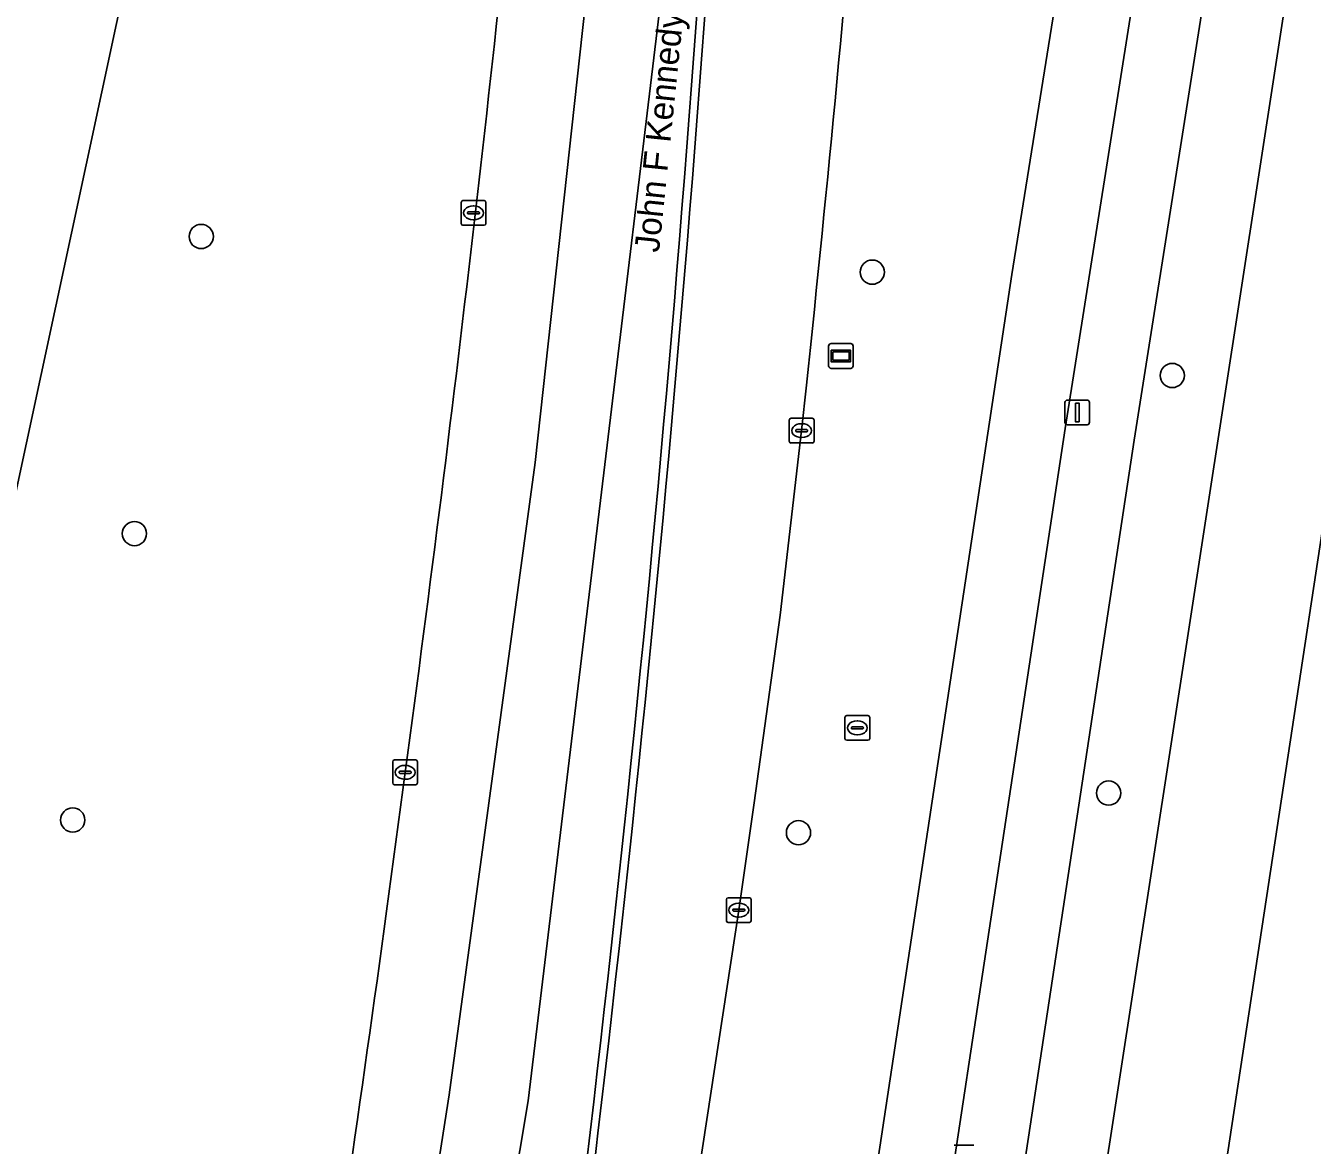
# Model space of a CAD drawing. Extents: x 161758 to 162722, y 384793 to 385405.
# Drawn here: x 161822.4 to 161874.4, y 385053.9 to 385099.1 of the extents above; entities that cross this region are included whole.
import ezdxf

# ---------------------------------------------------------------- set-up
doc = ezdxf.new("R2010")
doc.units = 0
for name, color, linetype in [('IMGEO_Berm_groen', 7, 'Continuous'), ('IMGEO_Boom', 7, 'Continuous'), ('IMGEO_Erf', 7, 'Continuous'), ('IMGEO_Fietspad_open', 7, 'Continuous'), ('IMGEO_Groenvoorziening', 7, 'Continuous'), ('IMGEO_Hek', 7, 'Continuous'), ('IMGEO_Kolk', 7, 'Continuous'), ('IMGEO_Lichtmast', 7, 'Continuous'), ('IMGEO_Openbare_ruimte_label', 7, 'Continuous'), ('IMGEO_Rijbaan_lokaal_open', 7, 'Continuous'), ('IMGEO_Rijbaan_regionaal_gesloten', 7, 'Continuous'), ('IMGEO_Rioolput', 7, 'Continuous'), ('IMGEO_Voetpad_open', 7, 'Continuous'), ('IMGEO_Wegwijzer', 7, 'Continuous')]:
    doc.layers.add(name, color=color, linetype=linetype)

msp = doc.modelspace()

# ---------------------------------------------------------------- linework, layer by layer
at = {"layer": 'IMGEO_Berm_groen'}
for points in [[(161862.222, 385089.066), (161867.535, 385122.216), (161881.319, 385208.219), (161882.409, 385215.357), (161882.64, 385217.117), (161883.068, 385221.062)], [(161842.635, 384958.805), (161843.029, 384961.875), (161848.422, 384997.787), (161862.222, 385089.066)], [(161853.937, 385084.588), (161853.743, 385082.758), (161852.871, 385075.308), (161851.83, 385067.734), (161851.205, 385063.4), (161848.122, 385043.24), (161844.782, 385021.036), (161841.441, 384998.802), (161837.654, 384973.607), (161835.818, 384961.758)]]:
    msp.add_lwpolyline(points, dxfattribs=at)
for points in [[(161832.166, 385127.543), (161825.07, 385129.091), (161797.302, 385000), (161795.542, 384991.822), (161802.405, 384988.861), (161804.796, 385000)], [(161825.07, 385129.091), (161832.166, 385127.543), (161804.796, 385000), (161802.405, 384988.861), (161795.542, 384991.822), (161797.302, 385000)]]:
    msp.add_lwpolyline(points, close=True, dxfattribs=at)
for centre, radius, start, end in [((160707.489, 385222.265), 1140.599, 352.27579, 354.544128), ((160724.749, 385203.725), 1135.456, 353.977202, 355.219785), ((160752.062, 385211.102), 1094.942, 350.170994, 352.54116)]:
    msp.add_arc(centre, radius, start, end, dxfattribs=at)
at = {"layer": 'IMGEO_Boom'}
for centre in [(161829.509, 385090.595), (161856.592, 385089.155), (161868.7, 385084.983), (161826.814, 385078.601), (161866.131, 385068.124), (161824.323, 385067.038), (161853.614, 385066.523)]:
    msp.add_circle(centre, 0.489, dxfattribs=at)
at = {"layer": 'IMGEO_Erf'}
msp.add_lwpolyline([(161880.923, 385119.329), (161863.287, 385003.273), (161862.79, 385000), (161854.635, 384944.828), (161890.389, 384901.27), (161895.384, 384909.442)], dxfattribs=at)
at = {"layer": 'IMGEO_Fietspad_open'}
for points in [[(161873.913, 385143.131), (161885.4, 385214.936), (161882.409, 385215.357), (161881.319, 385208.219), (161867.535, 385122.216), (161862.222, 385089.066), (161848.422, 384997.787), (161843.029, 384961.875), (161842.635, 384958.805)], [(161845.937, 384961.055), (161864.377, 385082.843), (161870.503, 385121.575), (161873.913, 385143.131)]]:
    msp.add_lwpolyline(points, dxfattribs=at)
at = {"layer": 'IMGEO_Groenvoorziening'}
for points in [[(161892.743, 385260.68), (161890.539, 385233.713), (161888.572, 385218.345), (161891.617, 385217.57), (161876.429, 385120.298), (161873.599, 385102.176), (161860.843, 385019.372), (161853.315, 384968.451), (161850.889, 384943.599), (161852.833, 384935.577), (161860.083, 384917.83), (161874.638, 384901.508), (161887.186, 384893.396), (161890.389, 384901.27), (161854.635, 384944.828), (161862.79, 385000), (161863.287, 385003.273), (161880.923, 385119.329), (161887.975, 385165.729), (161892.13, 385191.383), (161913.18, 385282.726), (161913.347, 385283.925), (161913.577, 385286.213)], [(161891.617, 385217.57), (161888.572, 385218.345), (161888.19, 385214.465), (161881.5, 385172.372), (161876.704, 385142.872), (161873.252, 385120.982), (161867.164, 385082.371), (161848.857, 384961.566)], [(161885.599, 384889.495), (161887.186, 384893.396), (161874.638, 384901.508), (161860.083, 384917.83), (161852.833, 384935.577), (161850.889, 384943.599), (161853.315, 384968.451), (161860.843, 385019.372), (161873.599, 385102.176), (161876.429, 385120.298), (161891.617, 385217.57)]]:
    msp.add_lwpolyline(points, dxfattribs=at)
at = {"layer": 'IMGEO_Hek'}
msp.add_lwpolyline([(161863.287, 385003.273), (161880.923, 385119.329)], dxfattribs=at)
at = {"layer": 'IMGEO_Kolk'}
for p, q in [((161839.999, 385091.121), (161839.999, 385091.973)), ((161840.074, 385092.047), (161840.926, 385092.047)), ((161840.301, 385091.59), (161840.699, 385091.59)), ((161840.487, 385091.827), (161840.512, 385091.827)), ((161841, 385091.973), (161841, 385091.121)), ((161840.926, 385091.047), (161840.074, 385091.047)), ((161840.258, 385091.541), (161840.258, 385091.553)), ((161840.696, 385091.504), (161840.298, 385091.504)), ((161840.51, 385091.267), (161840.485, 385091.267)), ((161840.742, 385091.553), (161840.742, 385091.541)), ((161853.317, 385083.258), (161854.169, 385083.258)), ((161853.242, 385082.332), (161853.242, 385083.184)), ((161853.501, 385082.752), (161853.501, 385082.764)), ((161853.544, 385082.801), (161853.942, 385082.801)), ((161853.73, 385083.038), (161853.755, 385083.038)), ((161853.985, 385082.764), (161853.985, 385082.752)), ((161854.243, 385083.184), (161854.243, 385082.332)), ((161854.169, 385082.258), (161853.317, 385082.258)), ((161853.939, 385082.715), (161853.541, 385082.715)), ((161853.753, 385082.478), (161853.728, 385082.478)), ((161837.238, 385068.537), (161837.238, 385069.389)), ((161837.313, 385069.463), (161838.165, 385069.463)), ((161837.726, 385069.243), (161837.751, 385069.243)), ((161838.239, 385069.389), (161838.239, 385068.537)), ((161837.497, 385068.957), (161837.497, 385068.969)), ((161837.935, 385068.92), (161837.537, 385068.92)), ((161837.54, 385069.006), (161837.938, 385069.006)), ((161837.981, 385068.969), (161837.981, 385068.957)), ((161838.165, 385068.463), (161837.313, 385068.463)), ((161837.749, 385068.683), (161837.724, 385068.683)), ((161850.704, 385062.974), (161850.704, 385063.826)), ((161850.779, 385063.9), (161851.631, 385063.9)), ((161851.192, 385063.68), (161851.217, 385063.68)), ((161851.705, 385063.826), (161851.705, 385062.974)), ((161850.963, 385063.394), (161850.963, 385063.406)), ((161851.401, 385063.357), (161851.003, 385063.357)), ((161851.006, 385063.443), (161851.404, 385063.443)), ((161851.215, 385063.12), (161851.19, 385063.12)), ((161851.447, 385063.406), (161851.447, 385063.394)), ((161851.631, 385062.9), (161850.779, 385062.9))]:
    msp.add_line(p, q, dxfattribs=at)
for points in [[(161839.999, 385091.121), (161839.999, 385091.973)], [(161840.074, 385092.047), (161840.926, 385092.047)], [(161841, 385091.973), (161841, 385091.121)], [(161840.926, 385091.047), (161840.074, 385091.047)], [(161853.317, 385083.258), (161854.169, 385083.258)], [(161853.242, 385082.332), (161853.242, 385083.184)], [(161854.243, 385083.184), (161854.243, 385082.332)], [(161854.169, 385082.258), (161853.317, 385082.258)], [(161837.238, 385068.537), (161837.238, 385069.389)], [(161837.313, 385069.463), (161838.165, 385069.463)], [(161838.239, 385069.389), (161838.239, 385068.537)], [(161838.165, 385068.463), (161837.313, 385068.463)], [(161850.704, 385062.974), (161850.704, 385063.826)], [(161850.779, 385063.9), (161851.631, 385063.9)], [(161851.705, 385063.826), (161851.705, 385062.974)], [(161851.631, 385062.9), (161850.779, 385062.9)]]:
    msp.add_lwpolyline(points, dxfattribs=at)
for centre, radius, start, end in [((161840.076, 385091.971), 0.0765, 91.552, 178.448), ((161840.076, 385091.971), 0.0765, 91.552, 178.448), ((161840.298, 385091.55), 0.0403, 85.8775, 175.7526), ((161840.703, 385091.552), 0.0386, 1.7309, 96.639), ((161840.924, 385091.971), 0.0765, 1.552, 88.448), ((161840.924, 385091.971), 0.0765, 1.552, 88.448), ((161840.076, 385091.123), 0.0765, 181.552, 268.448), ((161840.076, 385091.123), 0.0765, 181.552, 268.448), ((161840.295, 385091.54), 0.0366, 178.938, 274.7102), ((161840.699, 385091.547), 0.043, 264.8664, 352.4533), ((161840.924, 385091.123), 0.0765, 271.552, 358.448), ((161840.924, 385091.123), 0.0765, 271.552, 358.448), ((161853.319, 385083.182), 0.0765, 91.552, 178.448), ((161853.319, 385083.182), 0.0765, 91.552, 178.448), ((161854.167, 385083.182), 0.0765, 1.552, 88.448), ((161854.167, 385083.182), 0.0765, 1.552, 88.448), ((161853.541, 385082.761), 0.0403, 85.8775, 175.7526), ((161853.538, 385082.751), 0.0366, 178.938, 274.7102), ((161853.942, 385082.758), 0.043, 264.8664, 352.4533), ((161853.946, 385082.763), 0.0386, 1.7309, 96.639), ((161853.319, 385082.334), 0.0765, 181.552, 268.448), ((161853.319, 385082.334), 0.0765, 181.552, 268.448), ((161854.167, 385082.334), 0.0765, 271.552, 358.448), ((161854.167, 385082.334), 0.0765, 271.552, 358.448), ((161837.315, 385069.387), 0.0765, 91.552, 178.448), ((161837.315, 385069.387), 0.0765, 91.552, 178.448), ((161838.163, 385069.387), 0.0765, 1.552, 88.448), ((161838.163, 385069.387), 0.0765, 1.552, 88.448), ((161837.537, 385068.966), 0.0403, 85.8775, 175.7526), ((161837.534, 385068.956), 0.0366, 178.938, 274.7102), ((161837.938, 385068.963), 0.043, 264.8664, 352.4533), ((161837.942, 385068.968), 0.0386, 1.7309, 96.639), ((161837.315, 385068.539), 0.0765, 181.552, 268.448), ((161837.315, 385068.539), 0.0765, 181.552, 268.448), ((161838.163, 385068.539), 0.0765, 271.552, 358.448), ((161838.163, 385068.539), 0.0765, 271.552, 358.448), ((161850.781, 385063.824), 0.0765, 91.552, 178.448), ((161850.781, 385063.824), 0.0765, 91.552, 178.448), ((161851.629, 385063.824), 0.0765, 1.552, 88.448), ((161851.629, 385063.824), 0.0765, 1.552, 88.448), ((161851.003, 385063.403), 0.0403, 85.8775, 175.7526), ((161851, 385063.393), 0.0366, 178.938, 274.7102), ((161851.404, 385063.4), 0.043, 264.8664, 352.4533), ((161851.408, 385063.405), 0.0386, 1.7309, 96.639), ((161850.781, 385062.976), 0.0765, 181.552, 268.448), ((161850.781, 385062.976), 0.0765, 181.552, 268.448), ((161851.629, 385062.976), 0.0765, 271.552, 358.448), ((161851.629, 385062.976), 0.0765, 271.552, 358.448)]:
    msp.add_arc(centre, radius, start, end, dxfattribs=at)
for centre, major_axis, ratio, start_param, end_param in [((161840.486, 385091.547), (-0.387, 0.002), 0.722429, 4.712389, 7.853982), ((161840.511, 385091.547), (-0.39, 0.002), 0.717154, 1.570796, 4.712389), ((161853.729, 385082.758), (-0.387, 0.002), 0.722429, 4.712389, 7.853982), ((161853.754, 385082.758), (-0.39, 0.002), 0.717154, 1.570796, 4.712389), ((161837.725, 385068.963), (-0.387, 0.002), 0.722429, 4.712389, 7.853982), ((161837.75, 385068.963), (-0.39, 0.002), 0.717154, 1.570796, 4.712389), ((161851.191, 385063.4), (-0.387, 0.002), 0.722429, 4.712389, 7.853982), ((161851.216, 385063.4), (-0.39, 0.002), 0.717154, 1.570796, 4.712389)]:
    msp.add_ellipse(centre, major_axis=major_axis, ratio=ratio, start_param=start_param, end_param=end_param, dxfattribs=at)
at = {"layer": 'IMGEO_Lichtmast'}
for p, q in [((161864.371, 385083.093), (161864.371, 385083.893)), ((161864.371, 385083.893), (161864.371, 385083.093)), ((161864.471, 385083.993), (161865.261, 385083.993)), ((161865.261, 385083.993), (161864.471, 385083.993)), ((161865.361, 385083.893), (161865.361, 385083.093)), ((161865.361, 385083.093), (161865.361, 385083.893)), ((161865.261, 385082.993), (161864.471, 385082.993)), ((161864.471, 385082.993), (161865.261, 385082.993)), ((161859.904, 385053.907), (161860.694, 385053.907)), ((161860.694, 385053.907), (161859.904, 385053.907))]:
    msp.add_line(p, q, dxfattribs=at)
msp.add_lwpolyline([(161864.791, 385083.868), (161864.941, 385083.868), (161864.941, 385083.118), (161864.791, 385083.118), (161864.791, 385083.868)], dxfattribs=at)
for centre, start, end in [((161864.471, 385083.893), 90, 180), ((161864.471, 385083.893), 90, 180), ((161865.261, 385083.893), 0, 90), ((161865.261, 385083.893), 360, 90), ((161864.471, 385083.093), 180, 270), ((161864.471, 385083.093), 180, 270), ((161865.261, 385083.093), 270, 0), ((161865.261, 385083.093), 270, 0)]:
    msp.add_arc(centre, 0.1, start, end, dxfattribs=at)
at = {"layer": 'IMGEO_Rijbaan_lokaal_open'}
msp.add_lwpolyline([(161835.818, 384961.758), (161837.654, 384973.607), (161841.441, 384998.802), (161844.782, 385021.036), (161848.122, 385043.24), (161851.205, 385063.4), (161851.83, 385067.734), (161852.871, 385075.308), (161853.743, 385082.758), (161853.937, 385084.588)], dxfattribs=at)
for centre, radius, start, end in [((160724.749, 385203.725), 1135.456, 353.977202, 355.219785), ((160824.331, 385174.832), 1028.269, 351.672196, 356.128554)]:
    msp.add_arc(centre, radius, start, end, dxfattribs=at)
at = {"layer": 'IMGEO_Rijbaan_regionaal_gesloten'}
msp.add_lwpolyline([(161851.137, 385125.739), (161847.678, 385126.475), (161845.742, 385106.666), (161842.993, 385081.473), (161839.52, 385055.945), (161835.903, 385032.779), (161831.569, 385007.397), (161829.399, 384995.814), (161825.492, 384976.413), (161822.019, 384959.327), (161818.724, 384945.388), (161808.45, 384904.992), (161805.49, 384894.455), (161802.858, 384885.087), (161806.301, 384884.91), (161808.959, 384894.325), (161812.031, 384905.208), (161818.108, 384927.94), (161823.605, 384952.19), (161832.136, 384992.657), (161842.706, 385055.699)], close=True, dxfattribs=at)
for points in [[(161849.925, 385105.437), (161851.374, 385125.689), (161851.137, 385125.739), (161842.706, 385055.699), (161832.136, 384992.657), (161823.605, 384952.19), (161818.108, 384927.94), (161812.031, 384905.208), (161808.959, 384894.325), (161806.301, 384884.91), (161810, 384884.72), (161811.52, 384889.999), (161811.584, 384890.221), (161811.803, 384891.061), (161812.619, 384893.993), (161812.623, 384894.009), (161816.113, 384906.346), (161820.936, 384924.881), (161826.126, 384946.341)], [(161822.556, 384979.674), (161816.347, 384950.387), (161814.168, 384941.371), (161810.063, 384925.307), (161808.527, 384919.411), (161805.893, 384909.296), (161803.561, 384900.798), (161802.106, 384895.489), (161801.851, 384894.591), (161801.011, 384891.632), (161800.726, 384890.625), (161799.208, 384885.274), (161802.858, 384885.087), (161805.49, 384894.455), (161808.45, 384904.992), (161818.724, 384945.388), (161822.019, 384959.327), (161825.492, 384976.413), (161829.399, 384995.814), (161831.569, 385007.397), (161835.903, 385032.779), (161839.52, 385055.945), (161842.993, 385081.473), (161845.742, 385106.666)]]:
    msp.add_lwpolyline(points, dxfattribs=at)
for centre, radius, start, end in [((160707.489, 385222.265), 1140.599, 352.27579, 354.544128), ((160842.049, 385172.983), 1010.137, 351.628985, 356.165859), ((160842.049, 385172.983), 1010.137, 351.628985, 356.165859), ((160824.331, 385174.832), 1028.269, 351.672196, 356.128554), ((160752.062, 385211.102), 1094.942, 350.170994, 352.54116)]:
    msp.add_arc(centre, radius, start, end, dxfattribs=at)
at = {"layer": 'IMGEO_Rioolput'}
for p, q in [((161855.49, 385070.33), (161855.49, 385071.182)), ((161855.565, 385071.256), (161856.417, 385071.256)), ((161855.792, 385070.799), (161856.19, 385070.799)), ((161855.978, 385071.036), (161856.003, 385071.036)), ((161856.491, 385071.182), (161856.491, 385070.33)), ((161855.749, 385070.75), (161855.749, 385070.762)), ((161856.187, 385070.713), (161855.789, 385070.713)), ((161856.001, 385070.476), (161855.976, 385070.476)), ((161856.233, 385070.762), (161856.233, 385070.75)), ((161856.417, 385070.256), (161855.565, 385070.256))]:
    msp.add_line(p, q, dxfattribs=at)
for points in [[(161855.49, 385070.33), (161855.49, 385071.182)], [(161855.565, 385071.256), (161856.417, 385071.256)], [(161856.491, 385071.182), (161856.491, 385070.33)], [(161856.417, 385070.256), (161855.565, 385070.256)]]:
    msp.add_lwpolyline(points, dxfattribs=at)
for centre, radius, start, end in [((161855.567, 385071.18), 0.0765, 91.552, 178.448), ((161855.567, 385071.18), 0.0765, 91.552, 178.448), ((161855.789, 385070.759), 0.0403, 85.8775, 175.7526), ((161856.194, 385070.761), 0.0386, 1.7309, 96.639), ((161856.415, 385071.18), 0.0765, 1.552, 88.448), ((161856.415, 385071.18), 0.0765, 1.552, 88.448), ((161855.567, 385070.332), 0.0765, 181.552, 268.448), ((161855.567, 385070.332), 0.0765, 181.552, 268.448), ((161855.786, 385070.749), 0.0366, 178.938, 274.7102), ((161856.19, 385070.756), 0.043, 264.8664, 352.4533), ((161856.415, 385070.332), 0.0765, 271.552, 358.448), ((161856.415, 385070.332), 0.0765, 271.552, 358.448)]:
    msp.add_arc(centre, radius, start, end, dxfattribs=at)
for centre, major_axis, ratio, start_param, end_param in [((161855.977, 385070.756), (-0.387, 0.002), 0.722429, 4.712389, 7.853982), ((161856.002, 385070.756), (-0.39, 0.002), 0.717154, 1.570796, 4.712389)]:
    msp.add_ellipse(centre, major_axis=major_axis, ratio=ratio, start_param=start_param, end_param=end_param, dxfattribs=at)
at = {"layer": 'IMGEO_Voetpad_open'}
for points in [[(161867.164, 385082.371), (161873.252, 385120.982), (161870.503, 385121.575), (161864.377, 385082.843), (161845.937, 384961.055)], [(161848.857, 384961.566), (161867.164, 385082.371)]]:
    msp.add_lwpolyline(points, dxfattribs=at)
at = {"layer": 'IMGEO_Wegwijzer'}
for p, q in [((161854.831, 385085.372), (161854.831, 385086.172)), ((161854.831, 385086.172), (161854.831, 385085.372)), ((161854.931, 385086.272), (161855.721, 385086.272)), ((161855.721, 385086.272), (161854.931, 385086.272)), ((161855.821, 385086.172), (161855.821, 385085.372)), ((161855.821, 385085.372), (161855.821, 385086.172)), ((161855.721, 385085.272), (161854.931, 385085.272)), ((161854.931, 385085.272), (161855.721, 385085.272))]:
    msp.add_line(p, q, dxfattribs=at)
for points in [[(161854.932, 385086.004), (161855.72, 385086.004), (161855.72, 385085.54), (161854.932, 385085.54), (161854.932, 385086.004)], [(161854.997, 385085.939), (161854.997, 385085.605), (161855.655, 385085.605), (161855.655, 385085.939), (161854.997, 385085.939)]]:
    msp.add_lwpolyline(points, dxfattribs=at)
for centre, start, end in [((161854.931, 385086.172), 90, 180), ((161854.931, 385086.172), 90, 180), ((161855.721, 385086.172), 0, 90), ((161855.721, 385086.172), 360, 90), ((161854.931, 385085.372), 180, 270), ((161854.931, 385085.372), 180, 270), ((161855.721, 385085.372), 270, 0), ((161855.721, 385085.372), 270, 0)]:
    msp.add_arc(centre, 0.1, start, end, dxfattribs=at)

# ---------------------------------------------------------------- texts
at = {"layer": 'IMGEO_Openbare_ruimte_label'}
msp.add_text('John F Kennedylaan', height=1, rotation=84.1469, dxfattribs=at).set_placement((161847.985, 385089.924))

doc.saveas('drawing.dxf')
